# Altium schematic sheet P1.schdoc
size 297 x 209 mm; Device: Drawing-Symbol_A4; Symbol: Drawing-Symbol_A4; Company: 嘉立创EDA; Version: V1.0; Page Size: A4; @Project Name: 电源模块; @Update Date: 2026-06-30; @Create Date: 2026-06-30; @Board Name: Board1; @Page Name: P1; @Create Time: 10:45:58; @Page Count: 1; @Page No: 1; @Schematic Name: Schematic1; @Update Time: 10:45:58; @Assembly Variant: Basic; Border: 1; Title Block Position: 3; Size: A4; Width: 1170; Height: 825; Region Start: 1; X Region Count: 6; Y Region Count: 4; Blade Width: 10
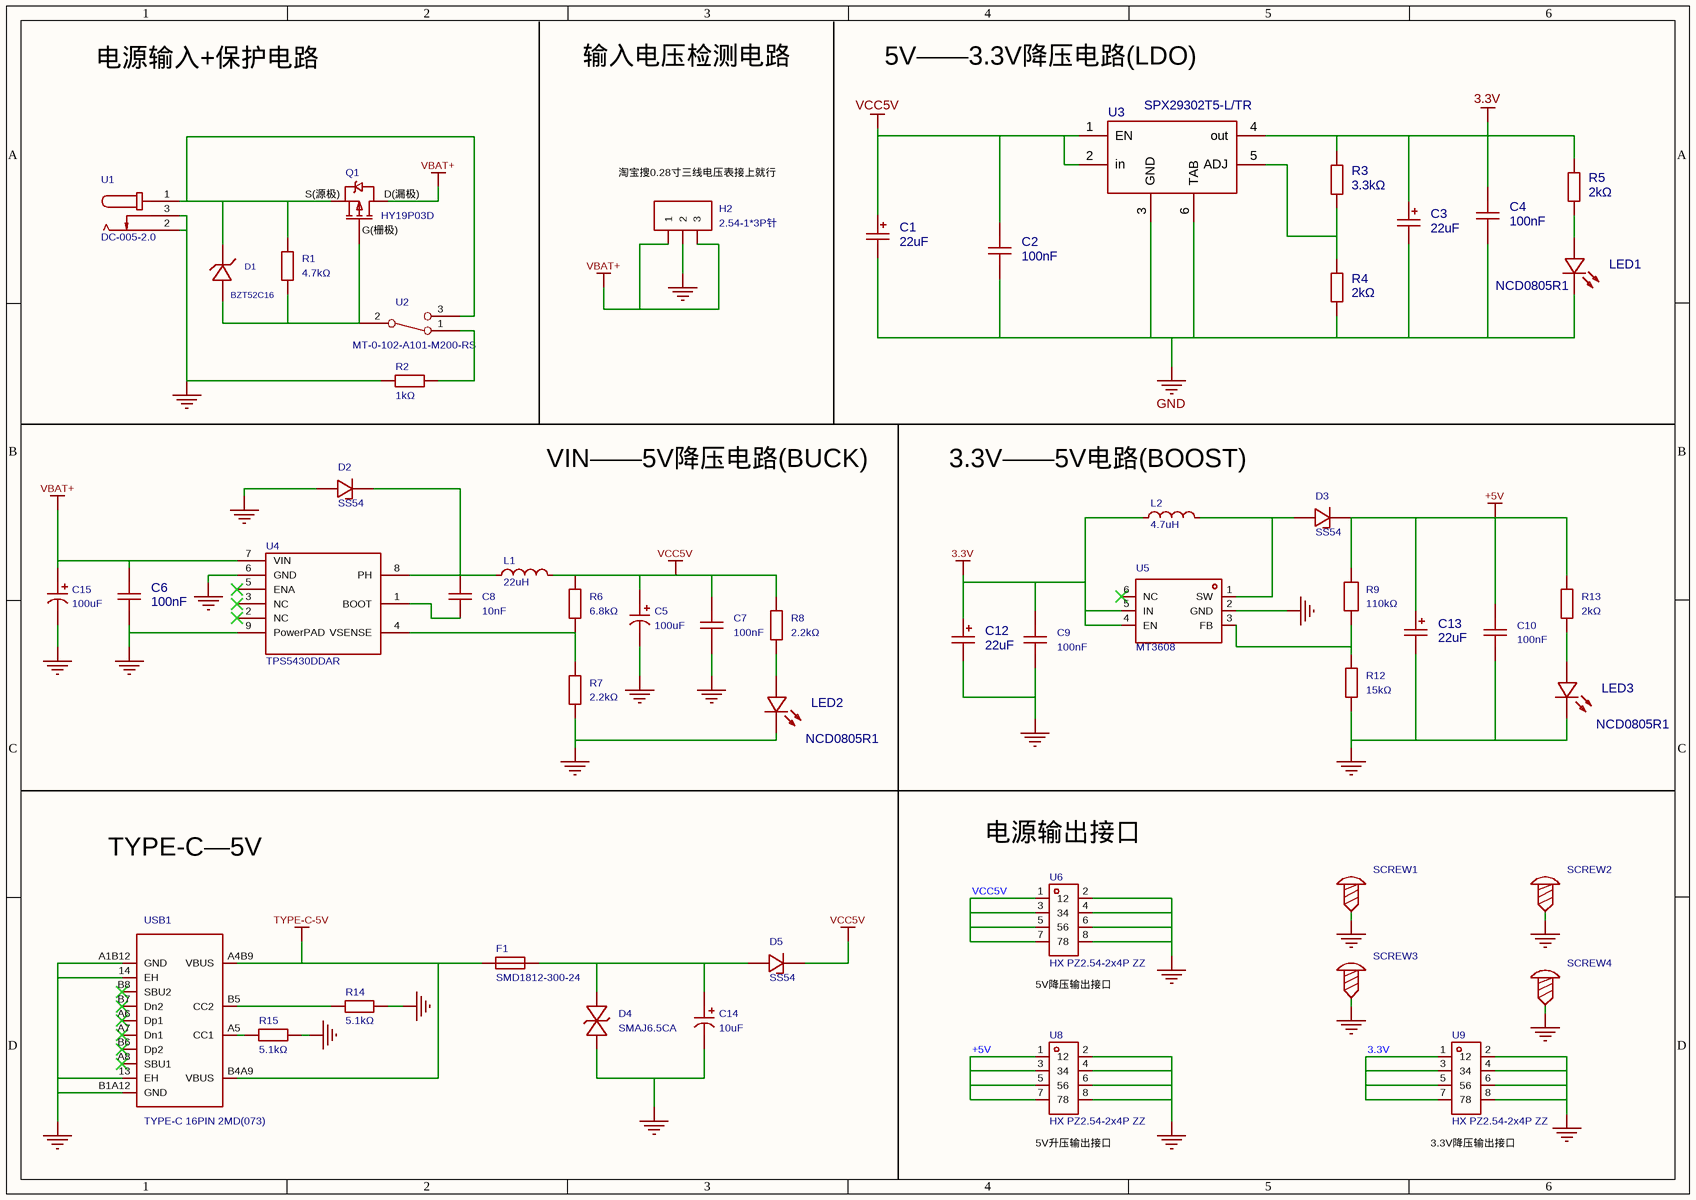
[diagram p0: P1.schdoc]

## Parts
C1  22uF  [CASE-B_3528]
C2  100nF  [C0805]
C3  22uF  [CASE-B_3528]
C4  100nF  [C0805]
C5  100uF  [CAP-SMD_L7.3-W4.3-RD_177EC0013]
C6  100nF  [C0805]
C7  100nF  [C0805]
C8  10nF  [C0805]
C9  100nF  [C0805]
C10  100nF  [C0805]
C12  22uF  [CASE-B_3528]
C13  22uF  [CASE-B_3528]
C14  10uF  [CAP-SMD_L2.1-W1.4-FD]
C15  100uF  [CAP-SMD_L7.3-W4.3-RD_177EC0013]
D1  BZT52C16  [SOD-123_L2.7-W1.6-LS3.7-RD]
D2  SS54  [SMA_L4.3-W2.6-LS5.0-FD]
D3  SS54  [SMA_L4.3-W2.6-LS5.0-FD]
D4  SMAJ6.5CA  [SMA-L4.3-W2.6-LS5.3-BI]
D5  SS54  [SMA_L4.3-W2.6-LS5.0-FD]
F1  SMD1812-300-24  [F1812]
H2  2.54-1*3P针  [HDR-TH_3P-P2.54-V-M-1]
L1  22uH  [IND-SMD_L4.6-W4.1-A]
L2  4.7uH  [IND-SMD_L4.6-W4.1-A]
LED1  NCD0805R1  [LED0805-RD]
LED2  NCD0805R1  [LED0805-RD]
LED3  NCD0805R1  [LED0805-RD]
Q1  HY19P03D  [TO-252-2_L6.6-W6.1-P4.57-LS9.9-TL-CW]
R1  4.7kΩ  [R0805]
R2  1kΩ  [R0805]
R3  3.3kΩ  [R0805]
R4  2kΩ  [R0805]
R5  2kΩ  [R0805]
R6  6.8kΩ  [R0805]
R7  2.2kΩ  [R0805]
R8  2.2kΩ  [R0805]
R9  110kΩ  [R0805]
R12  15kΩ  [R0805]
R13  2kΩ  [R0805]
R14  5.1kΩ  [R0805]
R15  5.1kΩ  [R0805]
SCREW1  (no value)  [M2螺丝]
SCREW2  (no value)  [M2螺丝]
SCREW3  (no value)  [M2螺丝]
SCREW4  (no value)  [M2螺丝]
U1  DC-005-2.0  [DC-IN-TH_DC-005-2.0_C22459640]
U2  MT-0-102-A101-M200-RS  [SW-TH_MT-0-103-A101-M200-RS]
U3  SPX29302T5-L/TR  [TO-263-5_L10.2-W9.9-P1.70-LS14.4-TL]
U4  TPS5430DDAR  [ESOP-8_L4.9-W3.9-P1.27-LS6.0-TL-EP]
U5  MT3608  [SOT-23-6_L2.9-W1.6-P0.95-LS2.8-BL]
U6  HX PZ2.54-2x4P ZZ  [HDR-TH_8P-P2.54-V-M-R2-C4-S2.54]
U8  HX PZ2.54-2x4P ZZ  [HDR-TH_8P-P2.54-V-M-R2-C4-S2.54]
U9  HX PZ2.54-2x4P ZZ  [HDR-TH_8P-P2.54-V-M-R2-C4-S2.54]
USB1  TYPE-C 16PIN 2MD(073)  [USB-C-SMD_TYPE-C-16PIN-2MD-073]

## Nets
3.3V: C3.1 C4.2 C9.2 C12.1 L2.1 R3.2 R5.2 U3.4(out) U5.4(EN) U5.5(IN) U9.1 U9.3 U9.5 U9.7
+5V: C10.2 C13.1 D3.2(K) R9.2 R13.2 U8.1 U8.3 U8.5 U8.7
GND: C1.2 C2.1 C3.2 C4.1 C5.1 C6.1 C7.1 C9.1 C10.1 C12.2 C13.2 C14.2 C15.1 D2.1(A) D4.1 H2.2 LED1.1(-) LED2.1(-) LED3.1(-) R2.2 R4.1 R7.1 R12.1 R14.2 R15.2 SCREW1.1 SCREW2.1 SCREW3.1 SCREW4.1 U1.2 U1.3 U3.3(GND) U3.6(TAB) U4.6(GND) U4.9(PowerPAD) U5.2(GND) U6.2 U6.4 U6.6 U6.8 U8.2 U8.4 U8.6 U8.8 U9.2 U9.4 U9.6 U9.8 USB1.13(EH) USB1.14(EH) USB1.A1B12(GND) USB1.B1A12(GND)
TYPE-C-5V: F1.1 USB1.A4B9(VBUS) USB1.B4A9(VBUS)
VBAT+: C6.2 C15.2 H2.1 H2.3 Q1.2(D) U4.7(VIN)
VCC5V: C1.1 C2.2 C5.2 C7.2 D5.2(K) L1.2 R6.2 R8.2 U3.1(EN) U3.2(in) U6.1 U6.3 U6.5 U6.7
NetC8_1: C8.1 U4.1(BOOT)
NetC8_2: C8.2 D2.2(K) L1.1 U4.8(PH)
NetC14_1: C14.1 D4.2 D5.1(A) F1.2
NetD1_1: D1.1(K) Q1.3(S) R1.2 U1.1 U2.3
NetD1_2: D1.2(A) Q1.1(G) R1.1 U2.2
NetD3_1: D3.1(A) L2.2 U5.1(SW)
NetLED1_2: LED1.2(+) R5.1
NetLED2_2: LED2.2(+) R8.1
NetLED3_2: LED3.2(+) R13.1
NetR2_1: R2.1 U2.1
NetR3_1: R3.1 R4.2 U3.5(ADJ)
NetR6_1: R6.1 R7.2 U4.4(VSENSE)
NetR9_1: R9.1 R12.2 U5.3(FB)
NetR14_1: R14.1 USB1.B5(CC2)
NetR15_1: R15.1 USB1.A5(CC1)

Not connected (* = marked no-connect by the designer): U4 2(NC)* 3(NC)* 5(ENA)*; U5 6(NC)*; USB1 A6(Dp1)* A7(Dn1)* A8(SBU1)* B6(Dp2)* B7(Dn2)* B8(SBU2)*

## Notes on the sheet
- 电源输入+保护电路
- 输入电压检测电路
- 5V——3.3V降压电路(LDO)
- (near Q1) S(源极)
- (near Q1) D(漏极)
- (near H2) 淘宝搜0.28寸三线电压表接上就行
- (near Q1) G(栅极)
- VIN——5V降压电路(BUCK)
- (near L2) 3.3V——5V电路(BOOST)
- TYPE-C—5V
- (near U6) 电源输出接口
- (near U6) 5V降压输出接口
- (near U8) 5V升压输出接口
- (near U9) 3.3V降压输出接口

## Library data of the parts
C1 C3 C12 C13 = TAJB226K016RNJ: 容值:22uF;精度:±10%;额定电压:16V;等效串联电阻(ESR):2.3Ω@100kHz;; Manufacturer: Kyocera AVX; Add into BOM: yes; 3D Model: b77bd53aeda446d2bdd09b0fdaf9418a0819f05c4eef4c71ace90d822a990e87; 3D Model Transform: 145.669,110.236,0,0,0,0,0,0,0; Tolerance: ±10%; Voltage Rating: 16V; ModelName: CASE-B_L3.5-W2.8-H1.9
C2 C4 C6 = CC0805KRX7R9BB104: 容值:100nF;精度:±10%;额定电压:50V;温度系数:X7R;; Manufacturer: YAGEO(国巨); Add into BOM: yes; 3D Model: 1ba041120af144c991958decab20d2410819f05c4eef4c71ace90d822a990e87; 3D Model Transform: 78.74,51.181,0,0,0,0,0,0.0005,0; Tolerance: ±10%; Voltage Rating: 50V; Temperature Coefficient: X7R; ModelName: C0805_L2.0-W1.3-H1.3
C5 C15 = TA10R0M100AR40: 容值:100uF;精度:±20%;额定电压:10V;等效串联电阻(ESR):40mΩ@100kHz;; Manufacturer: JIERR(捷而瑞); AddInBom: yes; Tolerance: ±20%; Voltage Rating: 10V; Current - Leakage: 100uA@20℃,2min; Ripple Current: 3.2A@100kHz; ModelId: 57a4bba5c484496b9c973bf4fd310b240819f05c4eef4c71ace90d822a990e87; ModelTransform: 287.401,169.291,0,0,0,0,0,0,0
C7 C9 C10 = CC0805KRX7R9BB104: 容值:100nF;精度:±10%;额定电压:50V;温度系数:X7R;; Manufacturer: YAGEO(国巨); AddInBom: yes; Tolerance: ±10%; Voltage Rating: 50V; Temperature Coefficient: X7R; ModelId: 1ba041120af144c991958decab20d2410819f05c4eef4c71ace90d822a990e87; ModelName: C0805_L2.0-W1.3-H1.3; ModelTransform: 78.74,51.181,51.181,0,0,0,0,0,0
C8 = CL21B103KBANNNC: 容值:10nF;精度:±10%;额定电压:50V;温度系数:X7R;; Manufacturer: SAMSUNG(三星); AddInBom: yes; Tolerance: ±10%; Voltage Rating: 50V; Temperature Coefficient: X7R; ModelId: 1ba041120af144c991958decab20d2410819f05c4eef4c71ace90d822a990e87; ModelName: C0805_L2.0-W1.3-H1.3; ModelTransform: 78.74,51.181,51.181,0,0,0,0,0,0
C14 = TAJP106M010RNJ: 容值:10uF;精度:±20%;额定电压:10V;等效串联电阻(ESR):6Ω;; Manufacturer: Kyocera AVX; AddInBom: yes; Tolerance: ±20%; Voltage Rating: 10V; Equivalent Series Resistance(ESR): 6Ω; ModelId: b8353ee2a32847568f70f1cec07897410819f05c4eef4c71ace90d822a990e87; ModelTransform: 80.709,53.15,0,180,0,0,0,0,0
D1 = BZT52C16_C173426: 二极管配置:1个独立式;稳压值(标称值):16V;稳压值(范围):15.2V~16.8V;耗散功率(Pd):500mW;; Manufacturer: MDD(辰达半导体); AddInBom: yes; Diode Configuration: 1个独立式; Zener Voltage(Nom): 16V; Reverse Leakage Current (Ir): 100nA@12V; Pd - Power Dissipation: 500mW; Impedance(Zzt): 40Ω; Tolerance: ±5%; ModelId: ad7e39f9e5534b3c96ffdc5532ebb4930819f05c4eef4c71ace90d822a990e87; ModelName: SOD-123_L2.7-W1.6-H1.4-LS3.7; ModelTransform: 146.026,62.992,0,180,0,0,0.0005,0,0
D2 D3 D5 = SS54_C7420369: 二极管配置:独立式;正向压降(Vf):550mV@5A;直流反向耐压(Vr):40V;整流电流:5A;; Manufacturer: R+O(宏嘉诚); AddInBom: yes; Diode Configuration: 独立式; Voltage - DC Reverse(Vr): 40V; Current - Rectified: 5A; Reverse Leakage Current (Ir): 50uA@40V; Operating Junction Temperature Range: -55℃~+125℃; Non-Repetitive Peak Forward Surge Current: 120A; ModelId: 7e24bebe6cd74171ae8c9de6fc5b78aa0819f05c4eef4c71ace90d822a990e87; ModelTransform: 198.4248,103.5431,0,180,0,0,-0.001,0,0
D4 = SMAJ6.5CA_C19077527: 极性:双向;反向截止电压(Vrwm):6.5V;钳位电压:11.2V;峰值脉冲电流(Ipp):35.7A@10/1000us;峰值脉冲功率(Ppp):400W@10/1000us;击穿电压:7.98V;; Manufacturer: R+O(宏嘉诚); AddInBom: yes; Polarity: 双向; Reverse Stand-Off Voltage (Vrwm): 6.5V; Clamping Voltage: 11.2V; Voltage - Breakdown: 7.98V; Reverse Leakage Current (Ir): 500uA; Number of Channels: 单路; level of protection: IEC 61000-4-2; Type: TVS; ModelId: 158e58edd1c6495db0cdb6a8ba85866f0819f05c4eef4c71ace90d822a990e87; ModelTransform: 208.661,105.1179,0,0,0,0,0,0,0
F1 = SMD1812-300-24: 耐压(Vmax):24V;最大电流(Imax):40A;保持电流(Ihold):3A;跳闸电流(Itrip):6A;; Manufacturer: R+O(宏嘉诚); AddInBom: yes; Voltage - Max: 24V; Current - Max: 40A; Hold Current: 3A; Trip Current: 6A; Power Dissipation: 1.4W; Resistance - Initial (Ri) (Min): 10mΩ; Resistance - Post Trip (R1) (Max): 50mΩ; Time to Trip(Max): 4s; ModelId: bca21e458c564d38b781621ca22e660b0819f05c4eef4c71ace90d822a990e87; ModelName: F1812_L4.5-W3.2-H1.0; ModelTransform: 177.165,125.984,0,0,0,0,0.0005,0,0
H2 = 2.54-1*3P针: 插针结构:1x3P;间距:2.54mm;行距:-;圆针/方针:方针;安装方式:直插;排数:单排;总PIN位数:3P;额定电流:3A;额定电压:-;配合针长度:6mm;塑高:2.5mm;端接针长度:3mm;触头材质:黄铜;触头镀层:金;工作温度:-40℃~+105℃;颜色:黑色;; Manufacturer: BOOMELE(博穆精密); Symbol: Header-Male-2.54_1x3; AddInBom: yes; Pin Structure: 1x3P; Pitch: 2.54mm; Circluar Pins/Square Pins: 方针; Current Rating: 3A; ModelId: 94a8ffe137b6410295cb18cd3ffd99db0819f05c4eef4c71ace90d822a990e87; ModelName: HDR-M-2.54_1x3; ModelTransform: 299.9994,100,0,0,0,0,0,0,-118.11
L1 = SRG0420-220-M: 电感值:22uH;精度:±20%;额定电流:1.2A;饱和电流(Isat):1.3A;类型:一体成型电感;; Manufacturer: JIERR(捷而瑞); AddInBom: yes; Tolerance: ±20%; Current Rating: 1.2A; Current - Saturation(Isat): 1.3A; DC Resistance(DCR): 500mΩ; Type: 一体成型电感; ModelId: 3b00517e351145dc8b8e2e52a7e5ed2c0819f05c4eef4c71ace90d822a990e87; ModelName: IND-SMD_L4.6-W4.1-H1.5; ModelTransform: 181.102,161.417,0,0,0,0,0,0,0
L2 = SRG0420-4R7-M: 电感值:4.7uH;精度:±20%;额定电流:3A;饱和电流(Isat):3.5A;类型:一体成型电感;; Manufacturer: JIERR(捷而瑞); AddInBom: yes; Tolerance: ±20%; Current Rating: 3A; Current - Saturation(Isat): 3.5A; DC Resistance(DCR): 105mΩ; Type: 一体成型电感; ModelId: 3b00517e351145dc8b8e2e52a7e5ed2c0819f05c4eef4c71ace90d822a990e87; ModelName: IND-SMD_L4.6-W4.1-H1.5; ModelTransform: 181.102,161.417,0,0,0,0,0,0,0
LED1-LED3 = NCD0805R1: 灯头类型:-;发光颜色:红色;正向压降(Vf):1.6V~2.6V;功率:65mW;正向电流:25mA;波长:615nm~630nm;二极管配置:独立二极管;透镜颜色:-;色温:-;发光强度:195mcd;发光角度:130°;载带方式:-;工作温度:-30℃~+85℃;; Manufacturer: 国星光电; Add into BOM: yes; 3D Model: b1c5ed7a4f6e46d3bc6f6cc7c20f3fea0819f05c4eef4c71ace90d822a990e87; 3D Model Transform: 79.527,49.2125,0,0,0,0,0,0,0; Illumination Color: 红色; Power(Watts): 65mW; Forward Current: 25mA; Peak Wavelength: 630nm; Diode Configuration: 独立二极管; Luminous Intensity: 195mcd; Viewing Angle: 130°
Q1 = HY19P03D: 类型:P沟道;漏源电压(Vdss):30V;连续漏极电流(Id):90A;功率(Pd):50W;导通电阻(RDS(on)@Vgs,Id):6mΩ@10V,45A;阈值电压(Vgs(th)@Id):3V@250uA;; Manufacturer: HUAYI(华羿微); AddInBom: yes; Type: P沟道; Drain Source Voltage (Vdss): 30V; Continuous Drain Current (Id): 90A; Power Dissipation (Pd): 50W; ModelId: ce57f84d66384067af8a68020b6de06d0819f05c4eef4c71ace90d822a990e87; ModelName: TO-252-2L-3P_L6.6-W6.1-H2.3-LS10.1-P4.6; ModelTransform: 259.842,390.52442,0,270,0,0,38.027,-0.598,0
R1 = 0805W8F4701T5E: 电阻类型:厚膜电阻;阻值:4.7kΩ;精度:±1%;功率:125mW;最大工作电压:150V;温度系数:±100ppm/℃;; Manufacturer: UNI-ROYAL(厚声); AddInBom: yes; Tolerance: ±1%; Power(Watts): 125mW; Overload Voltage (Max): 150V; ModelId: 37a81e68749a4138bd2dfa6897b24b850819f05c4eef4c71ace90d822a990e87; ModelName: R0805_L2.0-W1.3-H0.6; ModelTransform: 78.74,51.181,0,0,0,0,0,-0.0005,0
R2 = 0805W8F1001T5E: 电阻类型:厚膜电阻;阻值:1kΩ;精度:±1%;功率:125mW;最大工作电压:150V;温度系数:±100ppm/℃;; Manufacturer: UNI-ROYAL(厚声); AddInBom: yes; Tolerance: ±1%; Power(Watts): 125mW; Overload Voltage (Max): 150V; ModelId: 37a81e68749a4138bd2dfa6897b24b850819f05c4eef4c71ace90d822a990e87; ModelName: R0805_L2.0-W1.3-H0.6; ModelTransform: 78.74,51.181,0,0,0,0,0,-0.0005,0
R3 = 0805W8F3301T5E: 电阻类型:厚膜电阻;阻值:3.3kΩ;精度:±1%;功率:125mW;工作电压:150V;温度系数:±100ppm/℃;; Manufacturer: UNI-ROYAL(厚声); Add into BOM: yes; 3D Model: 37a81e68749a4138bd2dfa6897b24b850819f05c4eef4c71ace90d822a990e87; 3D Model Transform: 78.74,51.181,0,0,0,0,0,-0.0005,0; Tolerance: ±1%; Power(Watts): 125mW; Voltage-Supply(Max): 150V; ModelName: R0805_L2.0-W1.3-H0.6
R4 R5 = 0805W8F2001T5E: 电阻类型:厚膜电阻;阻值:2kΩ;精度:±1%;功率:125mW;工作电压:150V;温度系数:±100ppm/℃;; Manufacturer: UNI-ROYAL(厚声); Add into BOM: yes; 3D Model: 37a81e68749a4138bd2dfa6897b24b850819f05c4eef4c71ace90d822a990e87; 3D Model Transform: 78.74,51.181,0,0,0,0,0,-0.0005,0; Tolerance: ±1%; Power(Watts): 125mW; Voltage-Supply(Max): 150V; ModelName: R0805_L2.0-W1.3-H0.6
R6 = 0805W8F6801T5E: 电阻类型:厚膜电阻;阻值:6.8kΩ;精度:±1%;功率:125mW;工作电压:150V;温度系数:±100ppm/℃;; Manufacturer: UNI-ROYAL(厚声); AddInBom: yes; Tolerance: ±1%; Power(Watts): 125mW; Voltage-Supply(Max): 150V; ModelId: 37a81e68749a4138bd2dfa6897b24b850819f05c4eef4c71ace90d822a990e87; ModelName: R0805_L2.0-W1.3-H0.6; ModelTransform: 78.74,51.181,0,0,0,0,0,-0.0005,0
R7 R8 = 0805W8F2201T5E: 电阻类型:厚膜电阻;阻值:2.2kΩ;精度:±1%;功率:125mW;工作电压:150V;温度系数:±100ppm/℃;; Manufacturer: UNI-ROYAL(厚声); AddInBom: yes; Tolerance: ±1%; Power(Watts): 125mW; Voltage-Supply(Max): 150V; ModelId: 37a81e68749a4138bd2dfa6897b24b850819f05c4eef4c71ace90d822a990e87; ModelName: R0805_L2.0-W1.3-H0.6; ModelTransform: 78.74,51.181,0,0,0,0,0,-0.0005,0
R9 = FRC0805F1103TS: 电阻类型:厚膜电阻;阻值:110kΩ;精度:±1%;功率:125mW;工作电压:150V;温度系数:±100ppm/℃;; Manufacturer: FOJAN(富捷); AddInBom: yes; Tolerance: ±1%; Power(Watts): 125mW; Voltage-Supply(Max): 150V; ModelId: 37a81e68749a4138bd2dfa6897b24b850819f05c4eef4c71ace90d822a990e87; ModelName: R0805_L2.0-W1.3-H0.6; ModelTransform: 78.74,51.181,0,0,0,0,0,-0.0005,0
R12 = 0805W8F1502T5E: 电阻类型:厚膜电阻;阻值:15kΩ;精度:±1%;功率:125mW;工作电压:150V;温度系数:±100ppm/℃;; Manufacturer: UNI-ROYAL(厚声); AddInBom: yes; Tolerance: ±1%; Power(Watts): 125mW; Voltage-Supply(Max): 150V; ModelId: 37a81e68749a4138bd2dfa6897b24b850819f05c4eef4c71ace90d822a990e87; ModelName: R0805_L2.0-W1.3-H0.6; ModelTransform: 78.74,51.181,0,0,0,0,0,-0.0005,0
R13 = 0805W8F2001T5E: 电阻类型:厚膜电阻;阻值:2kΩ;精度:±1%;功率:125mW;工作电压:150V;温度系数:±100ppm/℃;; Manufacturer: UNI-ROYAL(厚声); AddInBom: yes; Tolerance: ±1%; Power(Watts): 125mW; Voltage-Supply(Max): 150V; ModelId: 37a81e68749a4138bd2dfa6897b24b850819f05c4eef4c71ace90d822a990e87; ModelName: R0805_L2.0-W1.3-H0.6; ModelTransform: 78.74,51.181,0,0,0,0,0,-0.0005,0
R14 R15 = 0805W8F5101T5E: 电阻类型:厚膜电阻;阻值:5.1kΩ;精度:±1%;功率:125mW;工作电压:150V;温度系数:±100ppm/℃;; Manufacturer: UNI-ROYAL(厚声); AddInBom: yes; Tolerance: ±1%; Power(Watts): 125mW; Voltage-Supply(Max): 150V; ModelId: 37a81e68749a4138bd2dfa6897b24b850819f05c4eef4c71ace90d822a990e87; ModelName: R0805_L2.0-W1.3-H0.6; ModelTransform: 78.74,51.181,0,0,0,0,0,-0.0005,0
SCREW1-SCREW4 = M2螺丝: Symbol: 螺丝孔; ConvertToPcb: yes
U1 = DC-005-2.0_C22459640: 连接器类型:DC电源插座;安装方式:弯插;触点内径:2mm;触点外径:6.3mm;额定电流:3A;额定电压:20V;; Manufacturer: HanElectricity(瀚源); AddInBom: yes; Connector Type: DC电源插座; Inside Contact Diameter: 2mm; Outside Contact Diameter: 6.3mm; Current Rating: 3A; Voltage Rating (Max): 20V; ModelId: 1536c764fdf948548c94e43221d5c3cd0819f05c4eef4c71ace90d822a990e87; ModelTransform: 559.054,372.08587,0,0,0,0,-139.763,86.614,-157.48
U2 = MT-0-102-A101-M200-RS: 电路结构:单刀双掷;工作寿命:-;额定电流:5A;额定电压(AC):125V;安装方式:直插;; Manufacturer: YUEN FUNG(源丰); Symbol: MT-0-102-A101-M200-RS+PJ; AddInBom: yes; Circuit: 单刀双掷; Switch Height: 28.6mm; Current Rating: 5A; Voltage Rating (AC): 125V; Actuator Type: 圆柱钮柄; ModelId: 00333f9652344e77a6fef9f3435a33d80819f05c4eef4c71ace90d822a990e87; ModelTransform: 511.81,432.84,0,0,0,0,0,0,-118.11
U3 = SPX29302T5-L/TR: 输出极性:正极;工作电压:16V;输出电压:1.25V~16V;输出电流:3A;电源纹波抑制比(PSRR):-;输出类型:可调;; Manufacturer: MaxLinear(迈凌); Add into BOM: yes; 3D Model: 4e421a816a7f4d57b8710832ddea550a0819f05c4eef4c71ace90d822a990e87; 3D Model Transform: 401.574,560.17797,0,270,0,0,38.773,0.078,0; Output Configuration: 正极; Voltage - Supply: 16V; Output Current: 3A; Voltage Dropout: 800mV@(3A); Noise: 400uVrms; Output Type: 可调; Number of Outputs: 1; ModelName: TO-263-5-5P_L10.2-W8.7-H4.5-LS14.4-P1.70
U4 = TPS5430DDAR: 功能类型:降压型;工作电压:5.5V~36V;输出电压:1.221V~32.04V;输出电流:3A;输出类型:可调;; Manufacturer: TI(德州仪器); Symbol: TPS5430DDAR_2; AddInBom: yes; Function: 降压型; Output Current: 3A; Frequency - Switching: 500kHz; Synchronous Rectifier: 否; Number of Outputs: 1; Topology: 降压式; Quiescent Current: 4.4mA; Switch tube (built-in/external): 内置; Output Type: 可调; ModelId: 821ddb58f3244ffb9a5d6f8174c5b14e0819f05c4eef4c71ace90d822a990e87; ModelTransform: 236.22,192.913,0,0,0,0,0,0,0
U5 = MT3608: 功能类型:升压型;工作电压:2V~24V;输出电压:600mV~28V;输出电流:2A;输出类型:可调;; Manufacturer: 西安航天民芯; AddInBom: yes; Function: 升压型; Voltage - Supply: 2V~24V; Output Current: 2A; Frequency - Switching: 1.2MHz; Synchronous Rectifier: 否; Number of Outputs: 1; Topology: 升压式; Quiescent Current: 100uA；1.6mA; Switch tube (built-in/external): 内置; Output Type: 可调; ModelId: 18da8f6c14a34920b3e136b5c401a1190819f05c4eef4c71ace90d822a990e87; ModelName: SOT-23-6_L2.9-W1.6-H1.5-LS2.8-P0.95; ModelTransform: 110.236,113.364,0,90,0,0,0.0005,0.0005,0
U6 U8 U9 = HX PZ2.54-2x4P ZZ: 插针结构:2x4P;间距:2.54mm;行距:2.54mm;圆针/方针:方针;安装方式:直插;排数:双排;总PIN位数:8P;额定电流:3A;额定电压:1kV;配合针长度:6mm;塑高:2.5mm;端接针长度:3mm;触头材质:铜合金;触头镀层:金;工作温度:-40℃~+105℃;颜色:黑色;; Manufacturer: hanxia(韩下); AddInBom: yes; Pin Structure: 2x4P; Pitch: 2.54mm; Circluar Pins/Square Pins: 方针; Current Rating: 3A; Voltage Rating (Max): 1kV; ModelId: 9655140a9899454ea9d6a6732d55fb0e0819f05c4eef4c71ace90d822a990e87; ModelName: HDR-TH_8P-P2.54-M-LI-2X4P; ModelTransform: 399.999,200,0,0,0,0,0,0,-118.11
USB1 = TYPE-C 16PIN 2MD(073): 连接器类型:Type-C;协议标准:-;公母:母;安装方式:卧贴;触点数量:16P;端口数量:1;额定电流 - 电源:3A;工作温度:-25℃~+85℃;; Manufacturer: SHOU HAN(首韩); Symbol: TYPE-C 16PIN 2MD(073)_2; AddInBom: yes; Gender: 母; Number of Contacts: 16P; Number of Ports: 1; Current Rating-Power: 3A; Voltage Rating: 5V; Connect-Disconnect Life: 1万次; Detection color: 黑色; ModelId: 3a41b9ec9b654a0fad4d118405ec62900819f05c4eef4c71ace90d822a990e87; ModelName: USB-C-SMD_TYPE-C-6PIN-2MD-073; ModelTransform: 351.9678,298.4246,0,0,0,0,0,-47.244,-35.433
